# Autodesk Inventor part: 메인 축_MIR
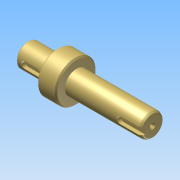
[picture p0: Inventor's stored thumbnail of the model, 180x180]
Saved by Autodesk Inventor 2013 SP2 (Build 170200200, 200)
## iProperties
Created: 2026-07
Part Number: 메인 축_MIR
Material: Generic
Document SubType Name: Modeling
Designer: aa
Density: 1 g/cm^3
Author: aa
변환 표준: STEP AP214IS
전처리기: Build: 200, Release: 2013 SP2 Update 6 - Date: Thu 07/17/2014
전송 단위: 밀리미터
불확실성: 0.01
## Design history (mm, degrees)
derived "메인 축.ipt"
feature "솔리드1::메인 축.ipt" dims "d0" = 10
tag "피쳐 태그1"
node "솔리드1"
